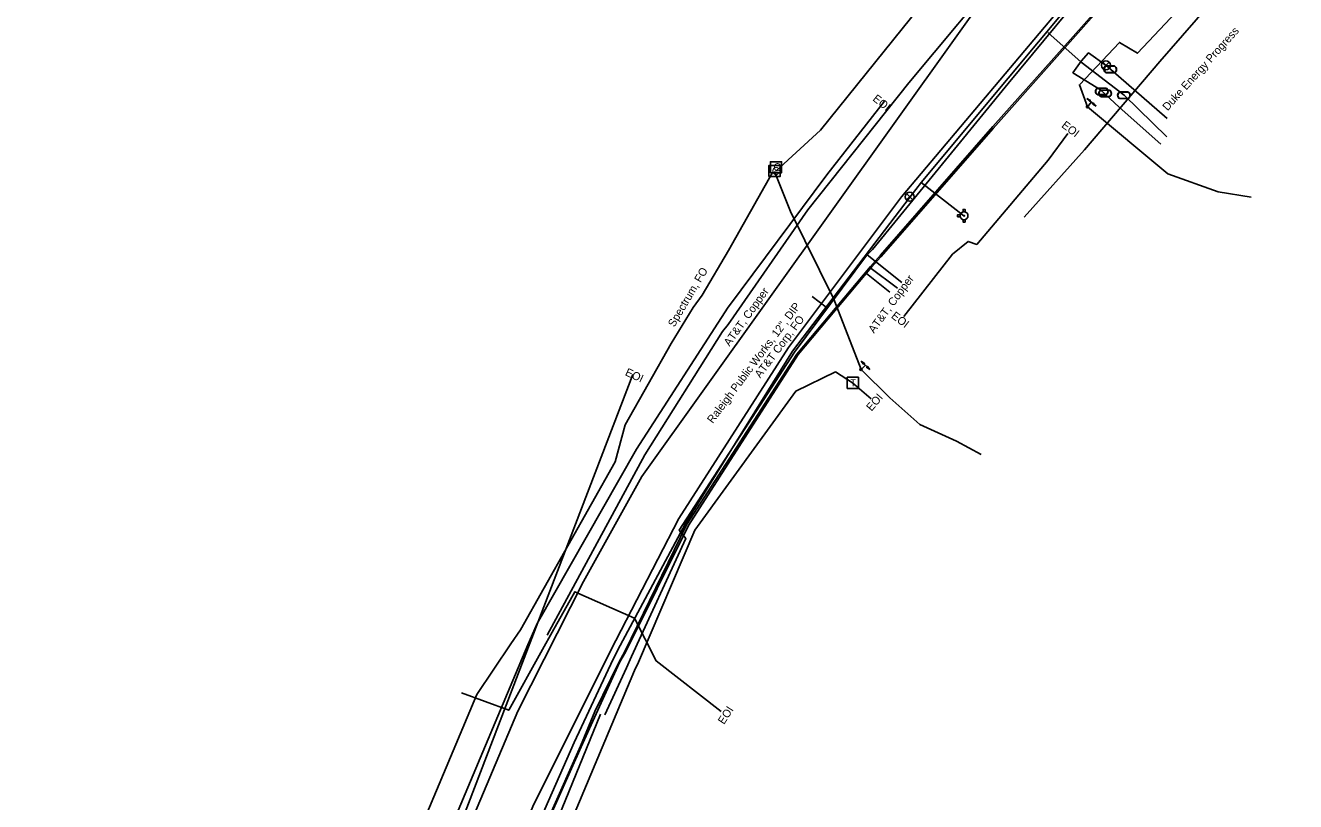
# Model space of a CAD drawing. Extents: x 2070721 to 2083039, y 729290 to 737883.
# Drawn here: x 2081248 to 2081883, y 734242 to 734630 of the extents above; entities that cross this region are included whole.
import ezdxf

# ---------------------------------------------------------------- set-up
doc = ezdxf.new("R2010")
doc.units = 0
for name, color, linetype in [('Cogo Default Point CELL', 7, 'Continuous'), ('COGO Default Point Elevation', 7, 'Continuous'), ('COGO Default Point Number', 7, 'Continuous'), ('Exist Utilities Gas UG Line SUE Cogo Point CELL', 7, 'Continuous'), ('Exist Utilities Gas UG Line SUE LOS B Cogo Comment', 7, 'Continuous'), ('Exist Utilities Gas UG Line SUE LOS B Cogo Point CELL', 7, 'Continuous'), ('Exist Utilities Gas Valve Cogo Elevation', 7, 'Continuous'), ('Exist Utilities Power UG Cable SUE LOS B Cogo Point CELL', 7, 'Continuous'), ('Exist Utilities Telephone Manhole Cogo Elevation', 7, 'Continuous'), ('Exist Utilities Telephone UG Cable SUE LOS C Cogo Comment', 7, 'Continuous'), ('Exist Utilities Telephone UG FO Cogo Point CELL', 7, 'Continuous'), ('Exist Utilities Telephone UG FO SUE LOS B Cogo Comment', 7, 'Continuous'), ('Exist Utilities TV Hand Hole CELL', 7, 'Continuous'), ('Exist Utilities TV Pedestal CELL', 7, 'Continuous'), ('Exist Utilities TV Pedestal Cogo Elevation', 7, 'Continuous'), ('Exist Utilities TV UG Cable Cogo Point CELL', 7, 'Continuous'), ('Exist Utilities TV UG Cable SUE LOS C Cogo Comment', 7, 'Continuous'), ('Exist Utilities TV UG Cable SUE LOS C Cogo Point CELL', 7, 'Continuous'), ('Exist Utilities TV UG FO Cable SUE LOS B Cogo Elevation', 7, 'Continuous'), ('Exist Utilities Water Meter CELL', 7, 'Continuous'), ('Exist Utilities Water Meter Cogo Number', 7, 'Continuous'), ('Exist Utilities Water UG Line SUE LOS B Cogo Elevation', 7, 'Continuous'), ('Exist Utilities Water Valve CELL', 7, 'Continuous')]:
    doc.layers.add(name, color=color, linetype=linetype)

msp = doc.modelspace()

# ---------------------------------------------------------------- linework, layer by layer
at = {"layer": 'Cogo Default Point CELL'}
for p, q in [((2081622.23, 734557.3), (2081622.23, 734557.3)), ((2081623, 734559.19), (2081623, 734559.19))]:
    msp.add_line(p, q, dxfattribs=at)
for points in [[(2081620.23, 734556.41), (2081625.78, 734556.41), (2081625.78, 734561.96), (2081620.23, 734561.96), (2081620.23, 734556.41)], [(2081619.45, 734554.52), (2081625, 734554.52), (2081625, 734560.07), (2081619.45, 734560.07), (2081619.45, 734554.52)]]:
    msp.add_lwpolyline(points, dxfattribs=at)
at = {"layer": 'COGO Default Point Elevation'}
for points in [[(2081789.43, 734611.72), (2081786.28, 734608.57), (2081787.85, 734610.15), (2081789.43, 734608.57), (2081786.28, 734611.72)], [(2081691.41, 734546.02), (2081688.26, 734542.87), (2081689.84, 734544.44), (2081691.41, 734542.87), (2081688.26, 734546.02)]]:
    msp.add_lwpolyline(points, dxfattribs=at)
for centre in [(2081787.85, 734610.15), (2081689.84, 734544.44)]:
    msp.add_circle(centre, 2.23, dxfattribs=at)
at = {"layer": 'COGO Default Point Number'}
msp.add_line((2081716.95, 734534.94), (2081716.95, 734534.94), dxfattribs=at)
for points in [[(2081716.44, 734536.85), (2081716.44, 734538.14), (2081717.47, 734538.14), (2081717.47, 734536.83)], [(2081715.04, 734535.45), (2081713.75, 734535.45), (2081713.75, 734534.43), (2081715.04, 734534.43)], [(2081716.44, 734533.03), (2081716.44, 734531.74), (2081717.47, 734531.74), (2081717.47, 734533.05)]]:
    msp.add_lwpolyline(points, dxfattribs=at)
for radius in [1.98, 0.243]:
    msp.add_circle((2081716.95, 734534.94), radius, dxfattribs=at)
at = {"layer": 'Exist Utilities Gas Valve Cogo Elevation'}
for p, q in [((2081668.5, 734515.35), (2081685.88, 734501.56)), ((2081668.21, 734506.12), (2081679.93, 734496.7)), ((2081669.89, 734509.05), (2081683.65, 734498.75))]:
    msp.add_line(p, q, dxfattribs=at)
at = {"layer": 'Exist Utilities Telephone UG Cable SUE LOS C Cogo Comment'}
for points in [[(2081599.02, 734480.52), (2081638.91, 734537.92), (2081689.31, 734601.45), (2081739.23, 734661.21), (2081776.34, 734700.28), (2081815.77, 734743.2), (2081849.28, 734780.93), (2081877.42, 734814.37), (2081912.75, 734856.19), (2081950.81, 734928.53), (2081978.43, 734978.59)], [(2081599.1, 734489.28), (2081599.22, 734489.45), (2081648.33, 734555.35), (2081677.16, 734592.15)], [(2081686.88, 734484.58), (2081711.27, 734515.79), (2081718.94, 734522.1), (2081723.27, 734520.61), (2081758.99, 734562.68), (2081768.79, 734576.06)], [(2081503.56, 734331.04), (2081553.34, 734418.19), (2081599.1, 734489.28)], [(2081508.66, 734325.21), (2081557.42, 734415.37), (2081596.29, 734477.07), (2081599.02, 734480.52)], [(2081306.2, 733834.68), (2081331.52, 733896.97), (2081357.74, 733949.48), (2081551.49, 734455.55)], [(2081422.3, 734128.51), (2081434.71, 734162.6), (2081462.76, 734234.36), (2081499.05, 734320.38), (2081503.56, 734331.04)]]:
    msp.add_lwpolyline(points, dxfattribs=at)
at = {"layer": 'Exist Utilities Telephone UG FO Cogo Point CELL'}
for p, q in [((2081790.05, 734608.13), (2081790.05, 734608.13)), ((2081785.8, 734597.09), (2081785.8, 734597.09)), ((2081787.45, 734596.09), (2081787.45, 734596.09)), ((2081796.84, 734595.2), (2081796.84, 734595.2))]:
    msp.add_line(p, q, dxfattribs=at)
for points in [[(2081792.09, 734606.57), (2081787.99, 734606.57)], [(2081792.09, 734606.43), (2081787.99, 734606.43)], [(2081788.01, 734609.83), (2081792.09, 734609.83)], [(2081788.01, 734609.69), (2081792.09, 734609.69)], [(2081787.83, 734595.53), (2081783.73, 734595.53)], [(2081787.83, 734595.39), (2081783.73, 734595.39)], [(2081783.76, 734598.79), (2081787.83, 734598.79)], [(2081783.76, 734598.66), (2081787.83, 734598.66)], [(2081789.48, 734594.53), (2081785.38, 734594.53)], [(2081789.48, 734594.39), (2081785.38, 734594.39)], [(2081785.41, 734597.79), (2081789.48, 734597.79)], [(2081785.41, 734597.66), (2081789.48, 734597.66)], [(2081798.88, 734593.64), (2081794.78, 734593.64)], [(2081798.88, 734593.5), (2081794.78, 734593.5)], [(2081794.81, 734596.9), (2081798.88, 734596.9)], [(2081794.81, 734596.76), (2081798.88, 734596.76)]]:
    msp.add_lwpolyline(points, dxfattribs=at)
for centre, radius, start, end in [((2081788.74, 734608.12), 1.86, 113.17804, 245.97939), ((2081788.75, 734608.12), 1.73, 115.30093, 243.78236), ((2081791.34, 734608.13), 1.86, 293.64832, 66.30838), ((2081791.35, 734608.13), 1.73, 295.12717, 64.87283), ((2081784.49, 734597.09), 1.86, 113.17804, 245.97939), ((2081784.5, 734597.09), 1.73, 115.30093, 243.78236), ((2081786.14, 734596.09), 1.86, 113.17804, 245.97939), ((2081786.15, 734596.09), 1.73, 115.30093, 243.78236), ((2081787.09, 734597.1), 1.86, 293.64832, 66.30838), ((2081787.1, 734597.09), 1.73, 295.12717, 64.87283), ((2081788.74, 734596.09), 1.86, 293.64832, 66.30838), ((2081788.75, 734596.09), 1.73, 295.12717, 64.87283), ((2081795.54, 734595.2), 1.86, 113.17804, 245.97939), ((2081795.55, 734595.2), 1.73, 115.30093, 243.78236), ((2081798.14, 734595.2), 1.86, 293.64832, 66.30838), ((2081798.15, 734595.2), 1.73, 295.12717, 64.87283)]:
    msp.add_arc(centre, radius, start, end, dxfattribs=at)
at = {"layer": 'Exist Utilities Telephone UG FO SUE LOS B Cogo Comment'}
msp.add_line((2081661.3, 734451.42), (2081661.3, 734451.42), dxfattribs=at)
msp.add_lwpolyline([(2081658.57, 734448.6), (2081664.16, 734448.6), (2081664.16, 734454.19), (2081658.57, 734454.19), (2081658.57, 734448.6)], dxfattribs=at)
at = {"layer": 'Exist Utilities TV Hand Hole CELL'}
msp.add_line((2081647.98, 734489.19), (2081641.02, 734494.48), dxfattribs=at)
at = {"layer": 'Exist Utilities TV Pedestal CELL'}
for points in [[(2081778.59, 734589.45), (2081774.62, 734600.43), (2081794.64, 734621.57), (2081803.63, 734616.23), (2081853.41, 734669.28), (2081872.71, 734694.38), (2081871.55, 734697.36), (2081875.65, 734699.45), (2081880.56, 734705.11), (2081892.44, 734706.39), (2081905.37, 734713.26), (2081917.92, 734727.97), (2081923.61, 734738.76)], [(2081622.95, 734557.31), (2081645.25, 734577.74), (2081708.9, 734656.89), (2081737.07, 734692.25)], [(2081621.16, 734556.51), (2081599.23, 734517.52), (2081586.14, 734495.22)], [(2081622.18, 734557.02), (2081630.2, 734537.03), (2081651.9, 734493.19), (2081665.48, 734458.07)], [(2081495.24, 734327.83), (2081542.69, 734411.91), (2081547.63, 734430.38), (2081570.62, 734471.08), (2081581.67, 734489.02), (2081586.14, 734495.22)], [(2081305.07, 733834.62), (2081318.51, 733883.96), (2081344.94, 733950.24), (2081370.6, 734023.22), (2081385.26, 734060), (2081415.18, 734152.65), (2081441.55, 734219.41), (2081473.57, 734295.5), (2081490.54, 734320.82), (2081495.24, 734327.83)]]:
    msp.add_lwpolyline(points, dxfattribs=at)
at = {"layer": 'Exist Utilities TV Pedestal Cogo Elevation'}
msp.add_line((2081695.6, 734551.63), (2081716.77, 734534.98), dxfattribs=at)
for points in [[(2081545.19, 734320.14), (2081577.78, 734381.02), (2081631.24, 734467.17), (2081690.06, 734544.38), (2081695.68, 734551.66), (2081723.83, 734585.62), (2081785.29, 734659.45), (2081832.89, 734707.14)], [(2081818.27, 734574.45), (2081796.99, 734595.16), (2081775.51, 734611.69), (2081758.88, 734626.61)], [(2081815.34, 734570.79), (2081794.4, 734589.2), (2081785.08, 734597.9), (2081771.35, 734606.46), (2081775.48, 734612.29), (2081779.08, 734616.33), (2081787.98, 734610), (2081790.24, 734608), (2081818.52, 734583.55)], [(2081490.29, 734199.14), (2081491.68, 734202.17), (2081522.1, 734271.61), (2081541.68, 734313.21), (2081545.19, 734320.14)]]:
    msp.add_lwpolyline(points, dxfattribs=at)
at = {"layer": 'Exist Utilities TV UG Cable Cogo Point CELL'}
for points in [[(2080953.21, 732796.69), (2081054.09, 733077.62), (2081111.09, 733245.57), (2081176.08, 733423.78), (2081231.97, 733580.28), (2081320.16, 733847.08), (2081418.84, 734093.09), (2081467.34, 734224.03), (2081494.06, 734287.2), (2081526.74, 734352.01), (2081556, 734404.62), (2081808.13, 734757.73), (2081845.73, 734804.26), (2081874.67, 734821.58), (2081898.66, 734810.94), (2081917.15, 734795.51)], [(2081675.15, 734515.17), (2081731.28, 734579.5), (2081761.87, 734613.73), (2081821.11, 734680.35), (2081882.55, 734750.91), (2081917.05, 734795.26)], [(2081675.44, 734514.41), (2081731.46, 734578.64), (2081762.11, 734613), (2081821.17, 734679.68), (2081882.84, 734750.34), (2081917.15, 734795.51)], [(2081671.19, 734518.01), (2081739, 734601.03), (2081786.76, 734658.83), (2081825.08, 734699.74), (2081848.94, 734723.65), (2081862.89, 734715.73), (2081883.59, 734698.93), (2081903.62, 734680.48), (2081932.44, 734654.41), (2081944.85, 734644.1)], [(2081550.8, 734314.52), (2081577.86, 734373.58), (2081574.68, 734377.67), (2081632.27, 734466.65), (2081668.29, 734515.1), (2081671.19, 734518.01)], [(2081547.42, 734317.11), (2081578.2, 734380.44), (2081633.4, 734465.71), (2081670.26, 734509.52), (2081675.15, 734515.17)], [(2081547.99, 734317.07), (2081579.24, 734380.05), (2081634.09, 734465.51), (2081670.76, 734509.17), (2081675.44, 734514.41)], [(2081554.35, 734311.73), (2081582.46, 734377.73), (2081632.84, 734447.21), (2081652.71, 734456.89)], [(2081652.71, 734456.89), (2081661.26, 734451.47), (2081670.58, 734443.46)], [(2081296.4, 733658.15), (2081287.8, 733664.8), (2081303.6, 733706.37), (2081324.3, 733763.14), (2081337.34, 733798.98), (2081373.91, 733899.45), (2081408.19, 733990.78), (2081432.67, 734050.1), (2081441.11, 734071.31), (2081457.65, 734065.9), (2081441.97, 734074.17), (2081465.76, 734134.1), (2081494.56, 734199.64), (2081510.1, 734235.63), (2081525.23, 734269.67), (2081532.48, 734287.03), (2081544.5, 734311.63), (2081547.42, 734317.11)], [(2081296.31, 733658.4), (2081289.16, 733664.06), (2081304.03, 733706.05), (2081324.8, 733762.93), (2081337.87, 733799.07), (2081374.5, 733899.39), (2081408.89, 733991.2), (2081433.1, 734049.99), (2081442.72, 734074.23), (2081467.51, 734133.17), (2081494.99, 734199.31), (2081510.48, 734235.4), (2081525.69, 734269.34), (2081544.76, 734311.53), (2081547.99, 734317.07)], [(2081537.47, 734285.43), (2081548.25, 734308.96), (2081550.8, 734314.52)], [(2081296.39, 733658.2), (2081307.45, 733685.25), (2081318.77, 733704.29), (2081345.73, 733792.08), (2081384.21, 733895.19), (2081416.52, 733988.47), (2081438.43, 734048.05), (2081472.15, 734132.3), (2081497.77, 734194.3), (2081521.27, 734233.79), (2081552.24, 734307.58), (2081554.35, 734311.73)], [(2081296.32, 733658.45), (2081292.23, 733667.87), (2081304.13, 733678.02), (2081310.51, 733703.91), (2081344.1, 733799.36), (2081380.98, 733896.99), (2081413.3, 733989.25), (2081435.43, 734048.8), (2081469.68, 734133.31), (2081498.8, 734198.46), (2081514.35, 734234.28), (2081535.34, 734285.71)]]:
    msp.add_lwpolyline(points, dxfattribs=at)
at = {"layer": 'Exist Utilities TV UG Cable SUE LOS C Cogo Comment'}
for points in [[(2081747.02, 734534.16), (2081777.19, 734567.94), (2081814.78, 734612), (2081844.33, 734646.12), (2081879.78, 734685.51), (2081910.59, 734706.71), (2081931.49, 734737.7), (2081947.42, 734760.31), (2081973.14, 734786.73), (2081997.07, 734814.98), (2082022.89, 734845.44), (2082040.83, 734835.09)], [(2081595.54, 734287.01), (2081563.06, 734312.34), (2081552.22, 734333.79), (2081522.51, 734346.94), (2081511.21, 734326.7)], [(2081511.21, 734326.7), (2081506.34, 734317.99), (2081489.43, 734287.72), (2081465.87, 734296.43)]]:
    msp.add_lwpolyline(points, dxfattribs=at)
at = {"layer": 'Exist Utilities TV UG Cable SUE LOS C Cogo Point CELL'}
for points in [[(2081542.88, 734322.62), (2081574.46, 734383.49), (2081629.3, 734469.05), (2081685.73, 734544.41), (2081784.03, 734661.28), (2081824.87, 734707.78), (2081827.69, 734710.71)], [(2081248.81, 733567.64), (2081281.2, 733657.22), (2081333.49, 733797.21), (2081369.06, 733900.16), (2081403.11, 733993), (2081427.18, 734053.08), (2081460.75, 734136.42), (2081485.85, 734201.8), (2081501.51, 734239.63), (2081538.45, 734313.8), (2081542.88, 734322.62)]]:
    msp.add_lwpolyline(points, dxfattribs=at)
at = {"layer": 'Exist Utilities Water UG Line SUE LOS B Cogo Elevation'}
for points in [[(2081778.59, 734589.45), (2081818.8, 734555.84), (2081843.88, 734546.87), (2081860.36, 734544.26)], [(2081665.48, 734458.07), (2081679.84, 734443.95), (2081694.88, 734430.56), (2081713.25, 734422.31), (2081725.44, 734415.53)]]:
    msp.add_lwpolyline(points, dxfattribs=at)
at = {"layer": 'Exist Utilities Water Valve CELL'}
for p, q in [((2081782.98, 734589.81), (2081778.4, 734593.63)), ((2081778.59, 734589.45), (2081780.57, 734591.82)), ((2081778.59, 734589.45), (2081778.59, 734589.45)), ((2081780.57, 734591.82), (2081782.98, 734589.81)), ((2081665.48, 734458.07), (2081667.64, 734460.27)), ((2081669.88, 734458.07), (2081665.63, 734462.25)), ((2081667.64, 734460.27), (2081669.88, 734458.07)), ((2081665.48, 734458.07), (2081665.48, 734458.07))]:
    msp.add_line(p, q, dxfattribs=at)
for points in [[(2081778.4, 734593.63), (2081780.13, 734592.63), (2081779.59, 734592.64), (2081779.69, 734592.16)], [(2081782.98, 734589.81), (2081781.24, 734590.81), (2081781.79, 734590.8), (2081781.69, 734591.28)], [(2081665.63, 734462.25), (2081667.27, 734461.11), (2081666.73, 734461.16), (2081666.79, 734460.67)], [(2081669.88, 734458.07), (2081668.23, 734459.2), (2081668.77, 734459.15), (2081668.72, 734459.64)]]:
    msp.add_lwpolyline(points, close=True, dxfattribs=at)
for centre in [(2081778.59, 734589.45), (2081665.48, 734458.07)]:
    msp.add_circle(centre, 0.517, dxfattribs=at)

# ---------------------------------------------------------------- texts
at = {"layer": 'Cogo Default Point CELL'}
for p in [(2081620.92, 734555.3), (2081621.69, 734557.19)]:
    msp.add_text('C', height=4, dxfattribs=at).set_placement(p)
at = {"layer": 'Exist Utilities Gas UG Line SUE Cogo Point CELL'}
msp.add_text('Raleigh Public Works, 12", DIP ', height=4, rotation=53.16319, dxfattribs=at).set_placement((2081591.38, 734430.81))
at = {"layer": 'Exist Utilities Gas UG Line SUE LOS B Cogo Comment'}
msp.add_text('AT&T Corp, FO', height=4, rotation=53.16883, dxfattribs=at).set_placement((2081615.13, 734453.47))
at = {"layer": 'Exist Utilities Gas UG Line SUE LOS B Cogo Point CELL'}
msp.add_text('Spectrum, FO', height=4, rotation=59.40022, dxfattribs=at).set_placement((2081572.15, 734478.94))
at = {"layer": 'Exist Utilities Power UG Cable SUE LOS B Cogo Point CELL'}
for rotation, p in [(321.29169, (2081670.98, 734592.84)), (322.47624, (2081765.33, 734579.52)), (322.47624, (2081680.23, 734484.19)), (335.04332, (2081547.25, 734455.32))]:
    msp.add_text('EOI', height=4, rotation=rotation, dxfattribs=at).set_placement(p)
at = {"layer": 'Exist Utilities Telephone Manhole Cogo Elevation'}
msp.add_text('EOI', height=4, rotation=49.41631, dxfattribs=at).set_placement((2081670.72, 734436.92))
at = {"layer": 'Exist Utilities Telephone UG FO SUE LOS B Cogo Comment'}
msp.add_text('T', height=3.42, dxfattribs=at).set_placement((2081660.16, 734449.71))
at = {"layer": 'Exist Utilities TV UG FO Cable SUE LOS B Cogo Elevation'}
msp.add_text('EOI', height=4, rotation=56.96084, dxfattribs=at).set_placement((2081596.98, 734280.28))
at = {"layer": 'Exist Utilities Water Meter CELL'}
msp.add_text('Duke Energy Progress', height=4, rotation=48.01251, dxfattribs=at).set_placement((2081818.66, 734587.13))
at = {"layer": 'Exist Utilities Water Meter Cogo Number'}
for rotation, p in [(53.85323, (2081671.96, 734475.9)), (54.47157, (2081599.77, 734469.36))]:
    msp.add_text('AT&T, Copper', height=4, rotation=rotation, dxfattribs=at).set_placement(p)

doc.saveas('drawing.dxf')
